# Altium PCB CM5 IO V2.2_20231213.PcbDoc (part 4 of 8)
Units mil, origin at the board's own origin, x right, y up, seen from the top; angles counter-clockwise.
Board outline 6299.61 x 3544.09 mil, 4 copper layers (Top, GND, Power, Bottom), stack 35.4 mil thick; 482 components, 404 nets, 1857 pads, 2731 vias.
Unrouted connection lines stored in the file: 1872.
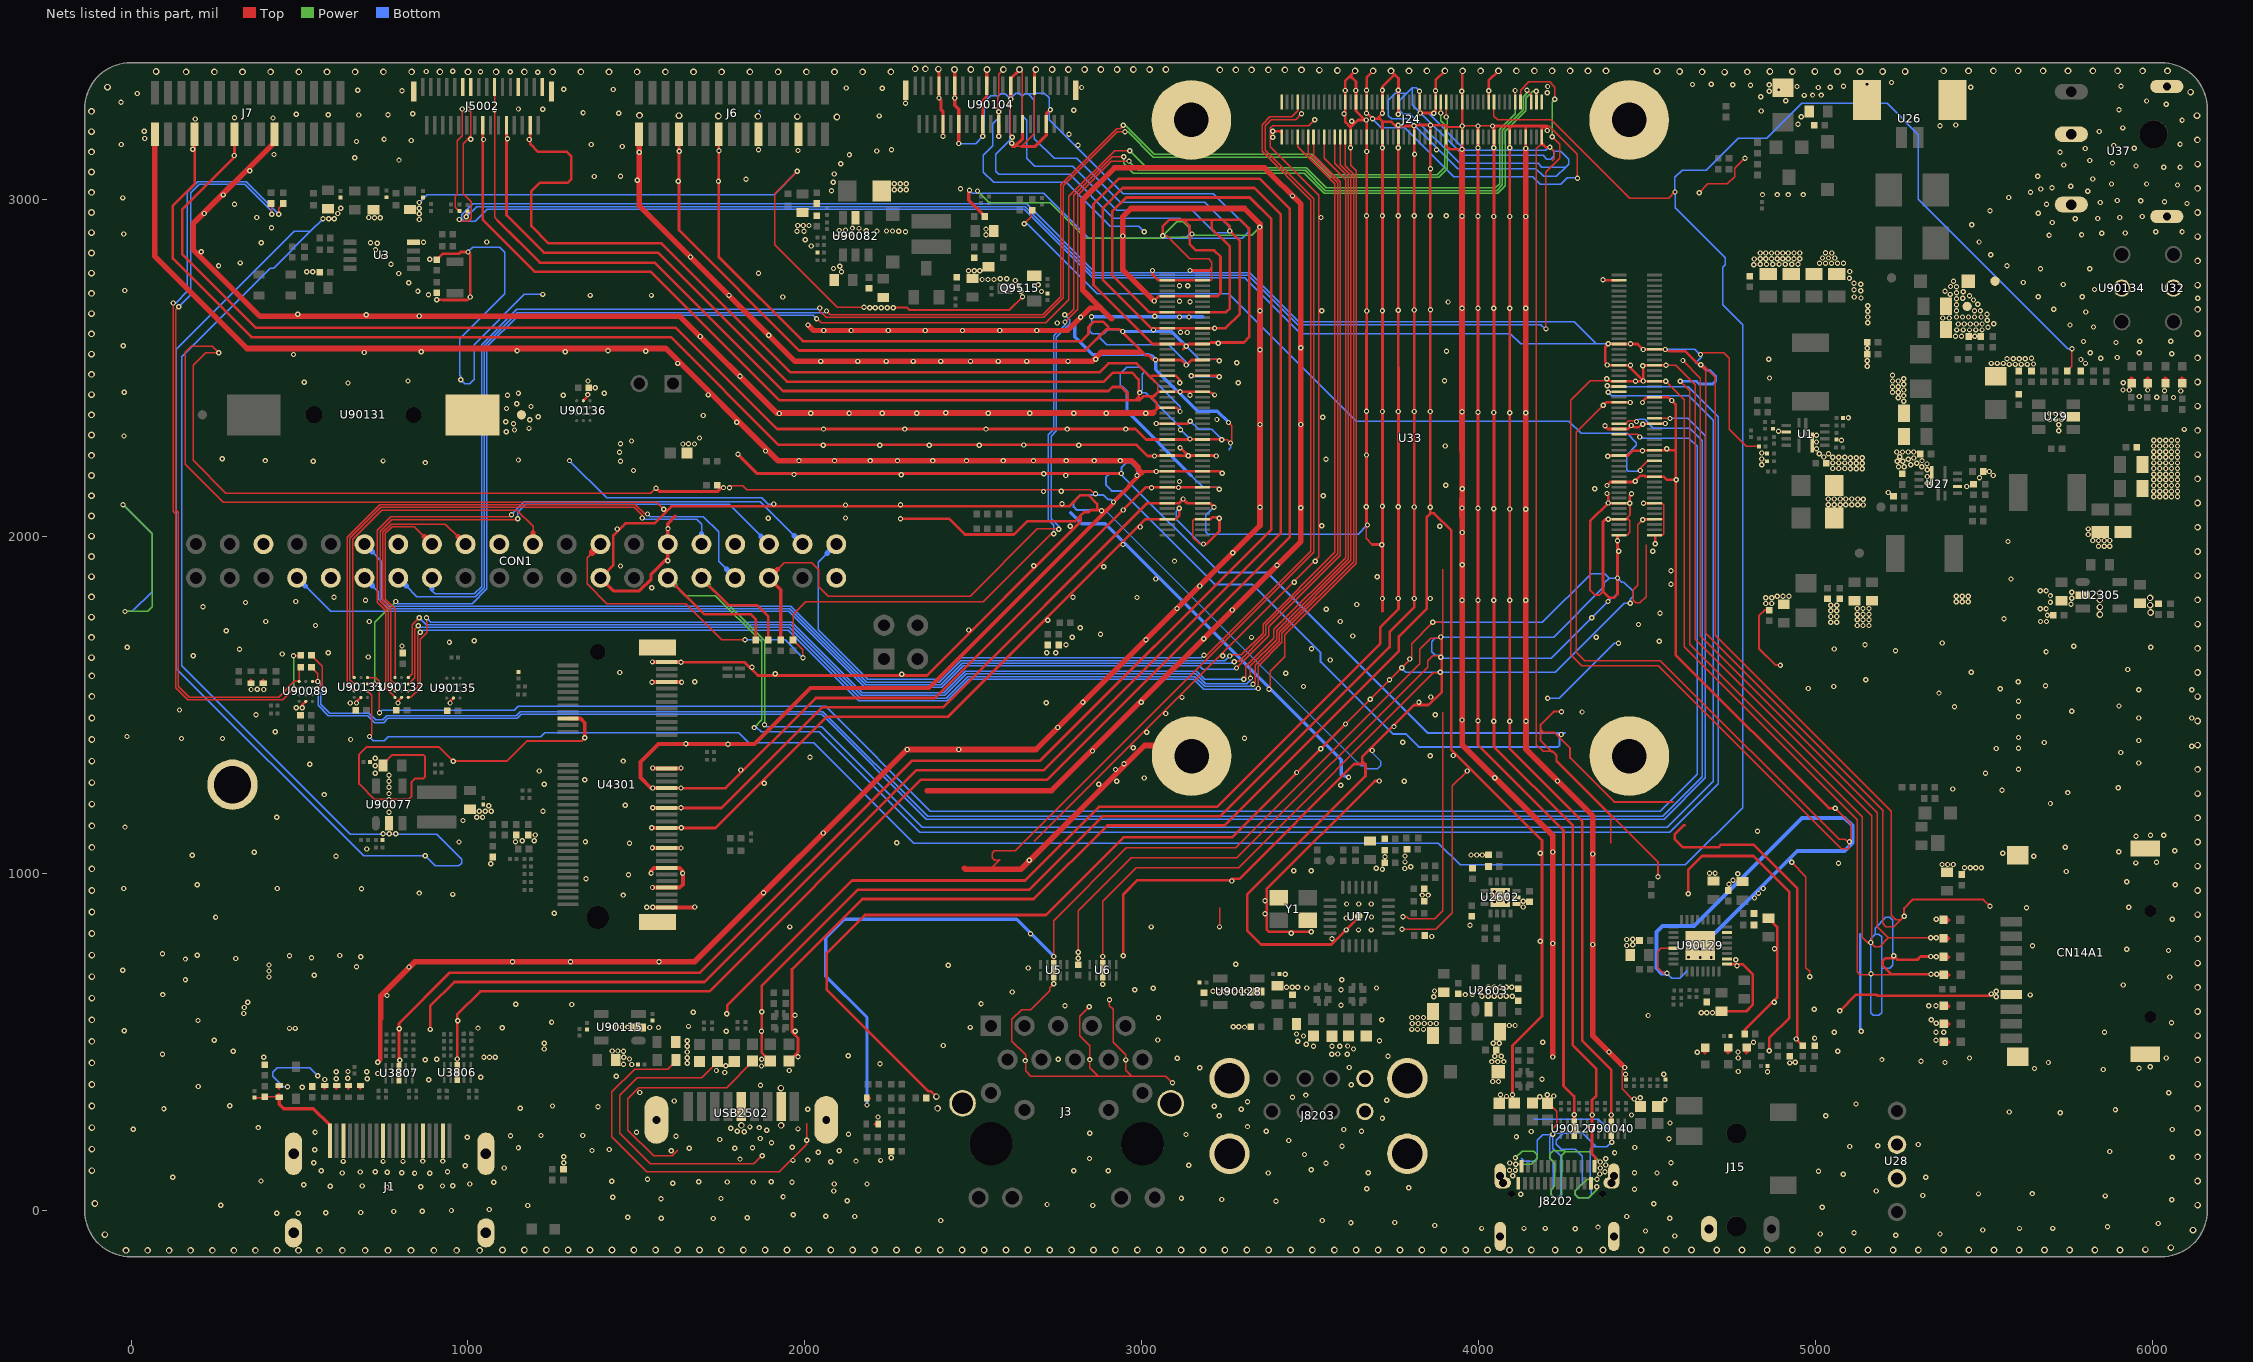
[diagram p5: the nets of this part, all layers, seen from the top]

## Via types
v1: diameter 15.75, hole 7.87, Top to Bottom, 2292 vias
v2: diameter 19.68, hole 11.81, Top to Bottom, 439 vias

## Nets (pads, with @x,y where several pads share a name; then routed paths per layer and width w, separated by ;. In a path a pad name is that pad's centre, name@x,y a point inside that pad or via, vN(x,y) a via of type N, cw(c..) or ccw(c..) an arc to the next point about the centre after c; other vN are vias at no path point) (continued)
GND: (continued)
  other v1: 4580.71,-76.77 5237.2,-74.8 5012.8,-70.87 5368.11,-70.87 5113.19,-66.93 4494.09,-62.01 5495.08,-59.06 4285.43,-55.12 4007.87,-54.13 4133.86,-54.13 4196.85,-54.13 5604.33,-54.13 5702.76,-54.13 4353.35,-50.2 5865.16,-49.21 3869.09,-45.28 6015.75,-39.37 3620.08,-37.4 3750,-36.42 2402.56,-30.51 3535.43,-30.51 1727.36,-24.61 1573.82,-23.62 4565.94,-23.62 1828.74,-22.64 1474.41,-20.67 2147.64,-18.7 4438.98,-18.7 2062.01,-17.72 1965.55,-13.78 432.09,-8.86 496.06,-8.86 577.76,-7.87 682.09,-6.89 779.53,-3.94 864.17,-2.95 950.79,-0.98 1062.99,1.97 5018.7,8.86 1177.17,13.78 2854.33,13.78 266.73,14.76 2718.5,16.73 4518.7,18.7 3397.64,26.57 2125,27.56 6056.1,30.51 3237.2,31.5 1572.83,33.46 1750.98,34.45 3117.13,35.43 1429.13,38.39 1935.04,39.37 5858.27,42.32 5316.93,43.31 4124.02,47.24 5482.28,48.23 5641.73,49.21 2085.63,57.09 5179.13,57.09 4461.61,62.01 3667.32,63.98 3791.34,66.93 759.84,68.9 860.24,69.88 591.54,70.87 686.02,71.85 924.21,71.85 954.72,72.83 512.8,75.79 1004.92,77.76 2086.61,77.76 2184.06,77.76 1607.28,79.72 4582.68,79.72 1076.77,82.68 1961.61,82.68 1769.69,83.66 1846.46,83.66 1685.04,84.65 1899.61,84.65 1426.18,85.63 385.83,86.61 1532.48,91.54 124.02,97.44 5325.79,97.44 4100.39,102.36 5080.71,106.3 4358.27,107.28 841.54,109.25 886.81,109.25 626.97,110.24 3375,110.24 4528.54,110.24 803.15,111.22 3671.26,111.22 4461.61,111.22 760.83,112.2 680.12,113.19 724.41,114.17 938.98,114.17 4374.02,114.17 5007.87,115.16 564.96,117.13 2797.24,117.13 2899.61,117.13 4090.55,118.11 4108.27,118.11 3501.97,120.08 1107.28,125 4360.24,125 992.13,131.89 3138.78,132.87 4375.98,133.86 3546.26,138.78 4091.54,139.76 542.32,140.75 1284.45,140.75 4569.88,140.75 2076.77,143.7 629.92,144.68 748.03,144.68 807.09,144.68 866.14,145.67 925.2,145.67 2151.57,145.67 1964.57,147.64 2224.41,147.64 2007.87,148.62 1807.09,151.57 4375.98,152.56 2844.49,153.54 2255.91,155.51 6057.09,157.48 1284.45,158.46 1873.03,161.42 3482.28,165.35 4402.56,170.28 2039.37,172.24 5872.05,174.21 1603.35,176.18 2101.38,176.18 1368.11,177.17 545.28,179.13 1419.29,180.12 1656.5,184.06 1791.34,184.06 1149.61,185.04 1844.49,185.04 4462.6,186.02 1962.6,187.01 5100.39,188.98 3593.5,189.96 5183.07,190.94 5304.13,194.88 1900.59,199.8 3436.02,206.69 2004.92,207.68 1747.05,209.65 4563.98,211.61 1867.13,212.6 998.03,216.54 4111.22,217.52 1617.13,219.49 1125.98,220.47 1216.54,221.46 1340.55,221.46 3130.91,224.41 2128.94,225.39 2845.47,228.35 546.26,231.3 1500,231.3 1819.88,232.28 4155.51,233.27 1799.21,234.25 3369.09,234.25 3651.57,234.25 1886.81,237.2 3598.43,239.17 6057.09,239.17 6.89,240.16 1979.33,241.14 1779.53,243.11 377.95,245.08 1864.17,245.08 1836.61,247.05 3312.99,248.03 4566.93,258.86 3713.58,272.64 2216.54,276.57 3229.33,280.51 5029.53,280.51 4336.61,282.48 4392.72,282.48 4452.76,282.48 4282.48,283.46 5725.39,289.37 5573.82,291.34 5888.78,298.23 2007.87,299.21 3294.29,299.21 97.64,301.18 1155.51,302.17 1385.83,307.09 3214.57,308.07 1250.98,309.06 293.31,310.04 5119.09,314.96 3312.99,321.85 1612.2,323.82 3726.38,325.79 4551.18,327.76 4478.35,333.66 3446.85,334.65 4180.12,336.61 4081.69,337.6 4222.44,338.58 3486.22,341.54 4063.98,342.52 4099.41,342.52 4202.76,342.52 6047.24,348.43 1509.84,349.41 507.87,365.16 199.8,367.13 1868.11,371.06 3621.06,372.05 4041.34,381.89 4058.07,381.89 883.86,386.61 574.8,387.8 4187.01,388.78 609.25,389.76 700.79,389.76 642.72,391.73 1037.4,394.09 1439.96,397.64 4435.04,403.54 4548.23,403.54 732.28,405.51 1761.81,408.46 609.25,410.43 699.8,410.43 4856.3,410.43 643.7,411.42 4769.69,411.42 1737.2,414.37 1953.74,414.37 5852.36,417.32 5648.62,420.28 5958.66,421.26 3171.26,422.24 3615.16,423.23 5992.13,425.2 1764.76,428.15 1870.87,427.95 1486.22,432.09 1461.61,433.07 2222.83,434.65 1650.59,436.02 4922.24,437.01 5382.87,437.99 5689.96,437.99 4938.98,438.98 4038.39,440.94 4056.1,440.94 4073.82,440.94 5312.01,441.93 2653.54,443.9 797.24,444.88 873.23,446.06 2951.77,445.87 2845.47,446.85 5195.87,446.85 907.48,447.83 1871.26,448.03 2751.97,447.83 968.5,448.82 1479.33,448.82 3104.33,450.79 4769.69,451.77 5455.71,451.77 6039.37,451.77 1650.59,452.76 393.7,453.74 1047.24,453.74 1063.98,453.74 1080.71,453.74 1462.6,453.74 4219.49,454.72 1979.33,455.71 3730.31,456.69 4047.24,456.69 4065.94,456.69 2128.74,457.87 93.5,462.6 3562.99,462.6 3609.25,462.6 3580.71,463.58 4647.64,468.5 1650.59,469.49 4385.83,469.49 4768.7,469.49 303.15,471.46 1461.61,471.46 5064.96,471.46 1428.15,472.44 1444.88,472.44 1226.38,478.35 3627.95,478.35 1650.59,486.22 3508.86,486.22 3563.98,486.22 3586.61,486.22 3610.24,487.2 2410.24,488.58 3487.2,492.13 1226.38,495.08 4042.32,495.08 4060.04,495.08 4188.98,498.03 4814.96,498.03 3462.6,500.98 1650.59,502.95 3704.72,502.95 247.05,503.94 5356.3,503.94 3047.24,504.92 4941.93,507.87 4996.06,509.84 3479.33,516.73 3458.66,522.64 5054.13,527.56 5356.3,527.56 5378.94,527.56 5856.3,527.56 1766.73,530.51 1871.06,530.51 1971.46,530.51 -19.69,532.48 3800.2,536.42 3817.91,536.42 3835.63,536.42 796.26,538.39 470.47,539.37 487.2,539.37 1029.53,540.35 1101.38,541.34 1539.76,542.13 1565.35,542.13 2490.16,542.32 1424.21,543.31 1440.94,543.31 1457.68,543.31 1474.41,543.31 3304.13,543.31 3270.67,544.29 3287.4,544.29 1654.53,545.28 4089.57,548.23 4107.28,548.23 3802.17,554.13 3819.88,554.13 3837.6,554.13 3855.31,554.13 3873.03,554.13 5357.28,555.12 6055.12,556.1 1248.03,558.07 969.49,562.01 198.82,562.99 3711.61,564.96 5342.52,564.96 3049.21,570.87 3800.2,571.85 3817.91,571.85 3835.63,571.85 4501.97,577.76 1970.47,578.74 1767.72,582.68 334.65,583.66 4659.45,585.63 4676.18,585.63 4692.91,585.63 1668.31,587.6 1872.05,588.58 4995.08,596.46 335.63,601.38 2771.65,606.3 5334.65,606.3 5356.3,606.3 3590.55,608.27 1308.07,610.24 1141.73,611.22 2522.64,612.2 346.46,617.13 4875.98,617.13 3866.14,632.87 5535.43,632.87 4008.86,634.84 4027.56,634.84 4045.28,634.84 4062.99,634.84 4080.71,634.84 4098.43,634.84 759.84,636.81 5635.83,638.78 94.49,639.76 3959.65,639.76 3980.31,639.76 2615.16,647.64 3210.63,649.61 3227.36,649.61 3244.09,649.61 3260.83,649.61 3277.56,649.61 3294.29,649.61 3311.02,649.61 5535.43,649.61 3868.11,650.59 4003.94,652.56 2978.35,654.53 3590.55,654.53 3033.07,658.27 3489.17,659.45 3695.87,659.45 3429.13,661.42 3445.87,661.42 3462.6,661.42 4027.56,661.42 4045.28,661.42 4062.99,661.42 4080.71,661.42 4097.44,661.42 5912.4,668.31 2883.86,670.47 161.42,684.06 3592.52,684.06 409.45,691.93 6050.2,691.93 543.31,696.85 3425.2,699.8 5358.27,699.8 5163.39,701.77 409.45,709.65 -24.61,711.61 2662.4,718.5 824.8,721.46 669.29,722.44 4765.75,725.39 409.45,727.36 2425.59,726.77 3278.54,729.33 1131.89,737.2 1304.13,737.2 1566.93,737.2 4761.81,743.11 161.42,745.08 311.02,747.05 2811.02,748.03 535.43,749.02 4656.5,750 4688.98,750 682.09,751.97 5357.28,751.97 2883.86,752.95 470.47,754.92 5231.3,754.92 619.09,755.91 196.85,756.89 93.5,760.83 2811.02,765.75 6046.26,770.67 4656.5,774.61 4687.99,774.61 5922.24,774.61 4622.05,775.59 4876.97,775.59 5642.72,784.45 4438.98,785.43 4456.69,787.4 4337.6,788.39 4219.49,791.34 4182.09,798.23 4438.98,803.15 4456.69,804.13 3563.98,805.12 5357.28,808.07 3860.24,812.01 2669.29,819.88 3442.91,821.85 3606.3,831.69 3642.72,831.69 3680.12,831.69 1954.72,840.55 3027.56,840.55 3973.43,845.47 5357.28,863.19 6057.09,863.19 3606.3,867.13 250.98,869.09 3681.1,870.08 3365.16,879.92 1255.91,880.91 5625,897.64 1530.51,898.62 5928.15,898.62 4131.89,899.61 3607.28,908.46 3643.7,908.46 3680.12,908.46 4080.71,914.37 4046.26,915.35 4131.89,916.34 3365.16,918.31 4817.91,926.18 1460.63,935.04 3831.69,935.04 3849.41,935.04 954.72,937.01 4829.72,939.96 855.31,940.94 1876.97,941.93 4046.26,945.87 4080.71,945.87 684.06,953.74 -21.65,954.72 434.06,954.72 4843.5,954.72 196.85,965.55 6065.94,965.55 4742.13,967.52 5922.24,974.41 4753.94,979.33 1350.39,983.27 1476.38,995.08 4767.72,998.03 4684.06,1000 4700.79,1000 5743.11,1004.92 3450.79,1006.89 3501.97,1006.89 3713.58,1011.81 3779.53,1013.78 3694.88,1014.76 5440.94,1015.75 5457.68,1015.75 5474.41,1015.75 5491.14,1015.75 3797.24,1018.7 5374.02,1025.59 5390.75,1025.59 5407.48,1025.59 1067.91,1027.56 5066.93,1029.53 5948.82,1030.51 6010.83,1032.48 3780.51,1033.46 2665.35,1038.39 3721.46,1049.21 608.27,1050.2 5646.65,1050.2 3780.51,1051.18 182.09,1053.15 3976.38,1054.13 3993.11,1054.13 4009.84,1054.13 4337.6,1057.09 4182.09,1059.06 5554.13,1059.06 366.14,1062.01 4219.49,1062.99 5898.62,1063.98 6064.96,1066.93 699.8,1071.85 5740.16,1076.77 1479.33,1088.58 2272.64,1090.55 973.43,1092.52 1140.75,1093.5 1348.43,1093.5 5099.41,1093.5 1161.42,1096.46 1196.85,1096.46 5949.8,1109.25 5993.11,1112.2 6032.48,1112.2 1199.8,1113.19 748.03,1117.13 766.73,1117.13 785.43,1117.13 2054.13,1119.09 4826.77,1124.02 1632.87,1134.84 -17.72,1136.81 985.24,1156.5 432.09,1166.34 1025.59,1166.34 1043.31,1166.34 765.75,1181.1 1033.46,1184.06 1051.18,1184.06 1068.9,1184.06 1222.44,1184.06 1631.89,1193.9 1062.01,1199.8 765.75,1200.79 1466.54,1201.77 5695.87,1206.69 573.82,1233.27 765.75,1236.22 5747.05,1239.17 5552.17,1246.06 5406.5,1250 1631.89,1252.95 5897.64,1253.94 765.75,1254.92 3589.57,1260.83 2871.54,1263.53 1226.38,1263.78 1878.94,1266.73 765.75,1272.64 2925.2,1272.64 3778.54,1272.64 4233.27,1273.62 1346.46,1277.56 3006.89,1282.48 4047.24,1283.46 765.75,1290.35 724.41,1296.26 5503.15,1296.46 3458.87,1298.99 1211.61,1303.15 1809.06,1306.1 2921.53,1307.83 5601.38,1308.07 724.41,1318.9 530.51,1322.83 2946.85,1324.8 5957.68,1326.77 1460.63,1332.68 724.41,1341.54 2014.76,1344.49 3855.31,1348.43 3924.21,1349.41 5904.53,1358.27 2853.13,1362.48 2303.15,1367.13 2456.69,1367.13 3530.7,1369.52 5535.43,1370.08 5601.38,1371.06 2974.13,1371.95 6115.16,1376.97 1771.65,1382.87 1646.65,1383.86 5677.17,1387.8 3773.62,1388.78 5957.68,1393.7 651.57,1396.65 149.61,1399.61 271.65,1399.61 3304.13,1400.59 5601.38,1402.56 -11.81,1405.51 4244.09,1411.42 3014.64,1418.58 428.15,1419.29 2750.04,1432.18 3748.03,1435.04 4044.29,1450.79 4091.54,1450.79 3997.05,1452.76 3949.8,1454.72 5957.68,1460.63 6115.16,1460.63 5601.38,1464.57 371.06,1470.47 3870.08,1470.47 3070.75,1473.81 4306.1,1478.35 5758.86,1480.31 143.7,1484.25 490.16,1491.14 5411.42,1494.09 5899.61,1496.06 650.59,1504.92 2715.55,1505.91 2824.8,1506.89 2998.18,1507.53 3821.91,1507.23 5601.38,1509.84 3677.41,1516.57 3118.84,1521.61 3857.28,1522.64 5365.16,1534.45 5957.68,1544.29 6115.16,1544.29 356.3,1545.28 393.7,1545.28 375,1546.26 3376.97,1546.26 5547.24,1547.24 4977.36,1548.23 3479.33,1554.13 5053.15,1554.13 5681.1,1556.1 1673.23,1568.11 5600.39,1567.91 3734.61,1574.03 5147.64,1573.82 2287.4,1590.55 1912.2,1592.13 3427.17,1593.5 1450,1595.67 5460.63,1596.46 5925.2,1604.33 1842.91,1611.42 3559.06,1632.87 3794.31,1635.56 703.74,1641.73 185.04,1645.67 3239.75,1645.45 448.82,1650.59 585.63,1654.53 2717.52,1654.53 2744.09,1654.53 5683.07,1657.48 5236.22,1660.43 321.85,1664.37 5054.13,1665.35 3502.95,1666.34 -10.83,1670.28 5994.09,1670.28 5764.76,1673.23 804.13,1674.21 2774.61,1678.15 5145.67,1678.15 5375,1683.07 944.88,1685.04 4535.43,1687.99 1018.7,1689.96 3011.97,1692.87 3183.14,1695.59 2793.31,1699.8 3325.05,1699.7 4348.43,1699.8 3625.98,1703.74 2876.97,1708.66 282.48,1719.49 2486.22,1721.46 2816.93,1728.35 547.24,1735.24 5123.03,1735.24 5139.76,1735.24 5157.48,1735.24 4473.43,1738.19 5044.29,1745.08 5062.01,1745.08 399.61,1747.05 706.69,1747.05 3588.58,1747.05 5666.34,1747.05 5684.06,1747.05 2720.47,1750.98 5123.03,1751.97 5139.76,1751.97 5157.48,1751.97 5558.07,1754.92 4334.65,1757.87 5044.29,1761.81 5062.01,1761.81 5687.01,1765.75 5123.03,1768.7 5139.76,1768.7 5157.48,1768.7 4537.4,1771.65 5044.29,1778.54 5062.01,1778.54 3268.12,1780.89 3547.24,1783.46 5665.35,1784.45 5683.07,1784.45 3104.13,1785.67 5123.03,1785.43 5139.76,1785.43 5157.48,1785.43 213.58,1790.35 5044.29,1795.28 5062.01,1795.28 3637.8,1797.24 5756.89,1798.23 4851.38,1800.2 4869.09,1800.2 339.57,1803.15 5695.87,1804.13 5416.34,1805.12 5434.06,1805.12 5451.77,1805.12 489.17,1806.1 695.87,1810.04 3949.8,1810.04 3997.05,1810.04 4044.29,1810.04 4091.54,1810.04 3713.58,1814.96 3760.83,1814.96 3808.07,1814.96 3855.31,1814.96 5758.86,1815.94 4851.38,1816.93 4869.09,1816.93 2985.24,1817.91 602.36,1818.9 2795.28,1818.9 4884.84,1821.85 4902.56,1821.85 4920.28,1821.85 5416.34,1821.85 5434.06,1821.85 5451.77,1821.85 5695.87,1823.82 5758.86,1833.66 5665.35,1838.58 5683.07,1838.58 1545.28,1847.44 3171.26,1852.36 4569.88,1857.28 3451.6,1863.58 3041.34,1873.03 5578.74,1873.03 3697.83,1879.92 4569.88,1897.64 2886.81,1909.45 1452.76,1911.42 2679.13,1912.4 3400.61,1913.79 3514.56,1925.37 3096.46,1926.18 1592.52,1927.17 3269.79,1950.83 4415.35,1955.71 4515.75,1955.71 5838.58,1970.47 5855.31,1970.47 5872.05,1970.47 2943.9,1975.39 5569.88,1984.25 5821.85,1987.2 5838.58,1987.2 5855.31,1987.2 5872.05,1987.2 5808.07,2004.92 1442.91,2021.26 5808.07,2021.65 1593.5,2022.64 2995.08,2027.56 2787.4,2029.53 3883.86,2029.53 3533.46,2031.5 1890.75,2053.15 2120.08,2054.13 2879.92,2075.79 2944.88,2077.76 4044.29,2081.69 4091.54,2080.71 3997.05,2082.68 3471.46,2084.65 3350.39,2085.63 3855.31,2085.63 3808.07,2086.61 3665.35,2087.6 3760.83,2087.6 3713.58,2088.58 2120.08,2092.52 5140.75,2092.52 2283.46,2093.5 5036.42,2093.5 5054.13,2093.5 5071.85,2093.5 5088.58,2093.5 5106.3,2093.5 5124.02,2093.5 2762.8,2096.46 5140.75,2109.25 5036.42,2110.24 5054.13,2110.24 5071.85,2110.24 5088.58,2110.24 5106.3,2110.24 5124.02,2110.24 6002.95,2117.13 6020.67,2117.13 6038.39,2117.13 6055.12,2117.13 6072.83,2117.13 3538.39,2120.08 4379.92,2126.97 5214.57,2129.92 2707.68,2132.87 2760.24,2133.86 6002.95,2133.86 6020.67,2133.86 6038.39,2133.86 6055.12,2133.86 6072.83,2133.86 4343.5,2140.75 3028.54,2143.7 5447.83,2147.64 6002.95,2150.59 6020.67,2150.59 6038.39,2150.59 6055.12,2150.59 6072.83,2150.59 3901.57,2151.57 5330.71,2157.48 3111.22,2162.4 6002.95,2167.32 6020.67,2167.32 6038.39,2167.32 6055.12,2167.32 6072.83,2167.32 5485.24,2173.23 5330.71,2177.17 2773.62,2180.12 5526.57,2180.12 2285.43,2182.09 1967.52,2183.07 6002.95,2184.06 6020.67,2184.06 6038.39,2184.06 6055.12,2184.06 6072.83,2184.06 2708.66,2185.04 5514.76,2191.93 1491.14,2194.88 5330.71,2196.85 5102.36,2199.8 5120.08,2199.8 5137.8,2199.8 5050.2,2200.79 5067.91,2200.79 5085.63,2200.79 6002.95,2200.79 6020.67,2200.79 6038.39,2200.79 6055.12,2200.79 6072.83,2200.79 5245.08,2205.71 5261.81,2205.71 5313.98,2205.71 4839.57,2211.61 5281.5,2211.61 5329.72,2214.57 5102.36,2216.54 5120.08,2216.54 5137.8,2216.54 5299.21,2216.54 5050.2,2217.52 5067.91,2217.52 5085.63,2217.52 6002.95,2217.52 6020.67,2217.52 6038.39,2217.52 6055.12,2217.52 6072.83,2217.52 873.03,2218.5 540.35,2222.44 1452.76,2222.44 5241.14,2222.44 5257.87,2222.44 748.03,2223.43 398.62,2224.41 1982.28,2224.41 2087.6,2224.41 2193.9,2224.41 2274.61,2224.41 2378.94,2224.41 2479.33,2224.41 2588.58,2224.41 2678.15,2224.41 2775.59,2224.41 2858.27,2224.41 2936.02,2224.41 5314.96,2224.41 1149.61,2226.38 3546.26,2228.35 5273.62,2228.35 4839.57,2229.33 270.67,2230.31 5290.35,2232.28 5102.36,2233.27 5120.08,2233.27 5137.8,2233.27 5050.2,2234.25 5067.91,2234.25 5085.63,2234.25 6002.95,2234.25 6020.67,2234.25 6038.39,2234.25 6055.12,2234.25 6072.83,2234.25 5023.62,2235.24 5249.02,2236.22 3666.34,2241.14 5009.84,2245.08 5037.4,2245.08 4839.57,2247.05 1449.8,2249.02 5240.16,2250 5256.89,2250 5273.62,2250 5290.35,2250 6002.95,2250.98 6020.67,2250.98 6038.39,2250.98 6055.12,2250.98 6072.83,2250.98 1882.87,2252.95 4557.09,2259.84 5001.97,2259.84 3899.61,2267.72 6002.95,2267.72 6020.67,2267.72 6038.39,2267.72 6055.12,2267.72 6072.83,2267.72 2054.13,2269.68 2221.46,2269.68 2369.09,2269.68 2516.73,2269.68 2812.01,2269.68 2649.61,2270.87 1637.8,2273.62 1672.24,2273.62 1452.76,2274.61 1654.53,2274.61 5001.97,2279.53 1485.24,2282.48 5075.79,2284.45 6002.95,2284.45 6020.67,2284.45 6038.39,2284.45 6055.12,2284.45 6072.83,2284.45 1687.01,2291.34 -20.67,2297.24 5001.97,2299.21 1113.19,2310.04 4888.78,2311.02 5720.47,2312.99 1137.8,2314.96 6093.5,2316.93 2055.12,2317.91 2296.26,2317.91 2537.4,2317.91 2778.54,2317.91 2951.77,2317.91 1181.1,2319.88 3350.39,2331.69 3471.46,2331.69 5720.47,2330.71 1134.84,2333.66 1797.24,2338.58 1112.2,2339.57 1183.07,2345.47 3222.44,2346.46 5693.9,2346.46 5711.61,2346.46 5729.33,2346.46 5096.46,2351.38 3536.42,2353.35 1208.66,2354.33 1697.83,2358.27 1923.23,2364.17 5693.9,2364.17 5711.61,2364.17 5729.33,2364.17 2016.73,2365.16 2130.91,2365.16 2229.33,2365.16 2331.69,2365.16 2544.29,2365.16 2667.32,2365.16 2797.24,2365.16 3010.83,2365.16 2417.32,2366.14 4091.54,2366.14 4044.29,2367.13 3997.05,2368.11 3713.58,2370.08 3760.83,2370.08 3808.07,2370.08 3855.31,2370.08 3666.34,2371.06 1114.17,2378.94 1187.01,2384.84 1144.69,2392.72 5260.83,2400.59 5244.09,2410.43 6061.02,2411.42 6011.81,2412.4 5959.65,2414.37 5260.83,2417.32 1117.13,2418.31 1282.48,2418.31 3142.72,2418.31 1712.6,2419.29 1149.61,2424.21 1404.53,2424.21 -19.69,2427.17 5227.36,2427.17 5244.09,2427.17 6082.68,2431.1 6034.45,2432.09 5260.83,2434.06 5911.42,2434.06 5930.12,2434.06 5984.25,2434.06 1377.95,2440.94 5227.36,2443.9 5244.09,2443.9 5260.83,2450.79 643.7,2454.72 513.78,2456.69 3285.43,2455.71 5912.4,2455.71 4464.57,2459.65 821.85,2460.63 1356.3,2460.63 5227.36,2460.63 5244.09,2460.63 3897.64,2461.61 5260.83,2467.52 4862.2,2469.49 1807.09,2474.41 5227.36,2477.36 5152.56,2503.94 4486.22,2505.91 4449.8,2506.89 4380.91,2507.87 5573.82,2509.84 5591.54,2509.84 5609.25,2509.84 5626.97,2509.84 5645.67,2510.83 1622.05,2512.8 5520.67,2512.8 5538.39,2512.8 5556.1,2512.8 5800.2,2512.8 3281.5,2514.76 2047.24,2518.7 2156.5,2518.7 2241.14,2518.7 2320.87,2518.7 2402.56,2518.7 2491.14,2518.7 2573.82,2518.7 2658.46,2518.7 2780.51,2518.7 5152.56,2520.67 5786.42,2524.61 2863.19,2525.59 4860.24,2525.59 5566.93,2526.57 5585.63,2526.57 5603.35,2526.57 5621.06,2526.57 5639.76,2528.54 5845.47,2528.54 5894.69,2530.51 482.28,2539.37 6056.1,2541.34 5813.98,2544.29 5959.65,2544.29 691.93,2545.28 861.22,2547.24 1288.39,2547.24 1527.56,2549.21 3903.54,2549.21 1145.67,2550.2 1415.35,2550.2 3350.39,2553.15 5152.56,2558.07 3471.46,2559.06 -22.64,2564.96 4449.8,2570.87 3226.38,2572.83 5890.75,2574.8 5794.29,2577.76 5960.63,2578.74 6053.15,2578.74 1688.98,2592.52 5414.37,2593.5 5432.09,2593.5 5471.46,2593.5 1892.72,2596.46 3134.84,2604.33 3114.17,2605.31 2056.1,2610.24 2136.81,2610.24 2247.05,2610.24 2357.28,2610.24 2467.52,2610.24 2577.76,2610.24 2687.99,2610.24 5418.31,2612.2 5437.01,2612.2 5455.71,2612.2 5474.41,2612.2 5493.11,2612.2 3215.55,2617.13 5510.83,2620.08 5823.82,2621.06 5753.94,2626.97 5422.24,2629.92 5439.96,2629.92 5457.68,2629.92 5475.39,2629.92 5493.11,2629.92 5527.56,2630.91 2749.02,2632.87 5153.54,2633.86 5508.86,2640.75 5375.98,2647.64 5395.67,2647.64 3111.22,2650.59 3139.76,2650.59 5153.54,2650.59 5417.32,2650.59 5435.04,2650.59 5452.76,2650.59 5470.47,2650.59 5490.16,2650.59 3038.39,2652.56 855.31,2653.54 697.83,2657.48 495.08,2658.46 5507.87,2658.46 5801.18,2665.35 5153.54,2667.32 3667.32,2668.31 3350.39,2669.29 3533.46,2669.29 3713.58,2669.29 5417.32,2669.29 5470.47,2669.29 5488.19,2669.29 3760.83,2670.28 3808.07,2671.26 3856.3,2672.24 5705.71,2673.23 3997.05,2676.18 4044.29,2676.18 4091.54,2676.18 2191.93,2678.15 2208.66,2678.15 2226.38,2678.15 2244.09,2678.15 5153.54,2684.06 5417.32,2687.01 5480.31,2687.99 3908.46,2694.88 3142.72,2695.87 3111.22,2696.85 5467.52,2700.79 5417.32,2704.72 5133.86,2706.69 5436.02,2705.71 6132.87,2705.71 1934.06,2709.65 5114.17,2709.65 5659.45,2710.63 5790.35,2710.63 5455.71,2713.58 1363.19,2714.57 1544.29,2714.57 1774.61,2714.57 882.87,2716.54 5398.62,2717.52 5417.32,2722.44 5437.01,2725.39 2701.77,2726.38 851.38,2727.36 2640.75,2727.36 5382.87,2727.36 5132.87,2728.35 -18.7,2729.33 5113.19,2731.3 5826.77,2732.28 5417.32,2740.16 5399.61,2741.14 2631.89,2743.11 3111.22,2743.11 3135.83,2743.11 2691.93,2746.06 5734.25,2747.05 5132.87,2748.03 5113.19,2750.98 823.82,2751.97 5615.16,2752.95 5408.46,2756.89 2624.02,2758.86 2525.59,2761.81 2543.31,2761.81 2561.02,2761.81 2579.72,2763.78 2598.43,2763.78 5099.41,2765.75 794.29,2779.53 1862.2,2780.51 521.65,2784.45 539.37,2784.45 2108.27,2784.45 5100.39,2785.43 2485.24,2787.4 2501.97,2787.4 2518.7,2787.4 5666.34,2793.31 5812.99,2793.31 2084.65,2794.29 2103.35,2801.18 259.84,2802.17 5566.93,2802.17 4815.94,2805.12 771.65,2807.09 4834.65,2807.09 4853.35,2807.09 4872.05,2807.09 4890.75,2807.09 4909.45,2807.09 4928.15,2807.09 4946.85,2807.09 5010.83,2810.04 5028.54,2810.04 5046.26,2810.04 5063.98,2810.04 5081.69,2810.04 323.82,2811.02 886.81,2821.85 4816.93,2822.83 4834.65,2823.82 4851.38,2823.82 4868.11,2823.82 4884.84,2823.82 4901.57,2823.82 4918.31,2823.82 4935.04,2823.82 4951.77,2823.82 5019.69,2825.79 5037.4,2825.79 5056.1,2825.79 1660.43,2828.74 748.03,2829.72 5518.7,2835.63 4834.65,2840.55 4851.38,2840.55 4868.11,2840.55 4884.84,2840.55 4901.57,2840.55 4918.31,2840.55 4935.04,2840.55 4951.77,2840.55 5047.24,2840.55 5028.54,2841.54 208.66,2844.49 725.39,2850.39 2018.7,2861.22 730.31,2869.09 386.81,2871.06 710.63,2871.06 868.11,2872.05 1056.1,2873.03 5484.25,2873.03 2000.98,2879.92 2092.52,2886.81 2114.17,2887.8 2942.91,2890.75 5691.93,2892.72 2537.4,2894.68 5788.39,2894.68 -21.65,2896.65 2134.84,2897.64 5848.43,2898.62 5918.31,2899.61 2298.23,2903.54 6008.86,2903.54 6086.61,2903.54 1976.38,2904.53 1997.05,2904.53 2278.54,2904.53 2213.58,2905.51 2242.13,2905.51 2259.84,2905.51 2182.09,2906.5 2101.38,2907.48 2120.08,2908.46 2537.4,2911.42 2160.43,2913.39 2140.75,2914.37 416.93,2915.75 1978.35,2922.24 1995.08,2922.24 2011.81,2922.24 5462.6,2924.21 5701.77,2931.1 855.31,2939.96 586.61,2941.93 603.35,2941.93 5769.69,2941.93 5836.61,2942.91 722.44,2944.88 739.17,2944.88 373.03,2945.87 705.71,2945.87 3531.5,2945.87 5901.57,2945.87 4044.29,2948.82 4091.54,2948.82 5968.5,2948.82 3997.05,2949.8 3666.34,2950.79 3713.58,2950.79 3760.83,2950.79 3808.07,2950.79 3855.31,2950.79 3902.56,2950.79 855.31,2956.69 217.52,2957.68 613.19,2957.68 5659.45,2958.66 5516.73,2965.55 622.05,2973.43 855.31,2973.43 307.09,2985.24 5684.06,2985.24 6101.38,2987.2 5843.5,2990.16 6034.45,2992.13 5963.58,2995.08 5894.69,2996.06 -24.61,3003.94 5571.85,3004.92 3446.85,3009.84 273.62,3012.8 4841.54,3013.78 4884.84,3013.78 4918.31,3013.78 4962.6,3013.78 5636.81,3020.67 5807.09,3023.62 2078.74,3025.59 2264.76,3028.54 2282.48,3028.54 2300.2,3028.54 5667.32,3030.51 2461.61,3031.5 5700.79,3034.45 5755.91,3038.39 6072.83,3042.32 5876.97,3045.28 5981.3,3045.28 2264.76,3046.26 2282.48,3046.26 2300.2,3046.26 2083.66,3050.2 1624.02,3053.15 1743.11,3053.15 1501.97,3056.1 1824.8,3059.06 5821.85,3060.04 1374.8,3067.32 1452.36,3068.5 5658.46,3067.91 2086.61,3074.8 352.36,3084.65 3856.3,3090.55 6032.48,3094.49 6080.71,3094.49 5949.8,3098.43 5735.24,3101.38 2106.3,3105.31 5879.92,3107.28 5812.99,3115.16 795.28,3116.14 664.37,3123.03 306.1,3129.92 2131.89,3131.89 424.21,3132.87 3809.06,3133.86 1507.87,3139.76 5724.41,3139.76 3667.32,3141.73 1626.97,3142.72 1745.08,3143.7 2212.6,3143.31 1979.33,3144.68 1862.2,3146.65 2256.89,3146.65 3874.02,3146.65 183.07,3148.62 5799.21,3150.59 5944.88,3151.57 3713.58,3152.56 3760.83,3152.56 3997.05,3152.56 4044.29,3152.56 1457.87,3156.3 5883.86,3159.45 2810.04,3160.43 -28.54,3162.4 1365.35,3162.2 6080.71,3163.39 669.29,3171.26 831.69,3174.21 1046.26,3177.17 750.98,3178.15 1007.87,3178.15 1117.13,3179.13 40.35,3180.12 3387.8,3184.06 2783.46,3192.91 5840.55,3200.79 39.37,3201.77 5910.43,3211.61 5368.11,3218.5 5415.35,3220.47 4946.85,3222.44 3623.03,3231.3 6086.61,3234.25 190.94,3238.19 421.26,3241.14 307.09,3242.13 4956.69,3245.08 2220.08,3247.24 676.18,3250 585.63,3250.98 762.8,3250.98 490.16,3251.97 835.63,3253.94 3599.41,3253.94 1447.24,3254.72 3666.34,3254.92 3713.58,3254.92 3866.14,3254.92 1341.54,3256.89 4837.6,3261.81 2797.24,3263.78 1078.74,3265.75 5899.61,3265.75 1221.46,3266.73 1149.61,3267.72 6039.37,3281.5 2298.23,3284.45 -29.53,3287.4 5981.3,3291.34 4910.43,3292.32 4836.61,3304.13 4965.55,3308.07 4990.16,3309.06 5015.75,3309.06 18.7,3313.98 4202.76,3315.94 3948.82,3320.87 4861.22,3320.87 804.13,3321.85 3871.06,3321.85 4029.53,3321.85 3603.35,3322.83 3634.84,3322.83 673.23,3323.82 3666.34,3323.82 3713.58,3323.82 3760.83,3323.82 1431.1,3325.59 4889.76,3324.8 1283.86,3326.38 2229.53,3329.13 2122.83,3329.92 2820.87,3331.69 5006.89,3331.69 5042.32,3332.68 5459.65,3332.68 4203.74,3334.65 4943.9,3334.65 5081.69,3335.63 5905.51,3335.63 4806.1,3338.58 4752.95,3339.57 4861.22,3339.57 4633.86,3340.55 4688.98,3341.54 5151.57,3341.54 5224.41,3346.46 1207.09,3376.38 1037.01,3378.35 875.98,3379.13 1125.59,3378.74 954.33,3379.92
  other v2: -14.76,-119.09 49.21,-119.09 113.19,-119.09 177.17,-119.09 241.14,-119.09 305.12,-119.09 369.09,-119.09 433.07,-119.09 497.05,-119.09 559.06,-119.09 626.97,-119.09 694.88,-119.09 762.8,-119.09 830.71,-119.09 898.62,-119.09 966.54,-119.09 1034.45,-119.09 1102.36,-118.11 1167.32,-118.11 1232.28,-118.11 1297.24,-118.11 1362.2,-118.11 1427.17,-118.11 1492.13,-118.11 1557.09,-118.11 1622.05,-118.11 1687.01,-118.11 1751.97,-118.11 1816.93,-118.11 1881.89,-118.11 1946.85,-118.11 2011.81,-118.11 2076.77,-118.11 2141.73,-118.11 2206.69,-118.11 2271.65,-118.11 2336.61,-118.11 2401.57,-118.11 2466.54,-118.11 2531.5,-118.11 2596.46,-118.11 2661.42,-118.11 2726.38,-118.11 2791.34,-118.11 2856.3,-118.11 2921.26,-118.11 2986.22,-118.11 3051.18,-118.11 3116.14,-118.11 3181.1,-118.11 3246.06,-118.11 3311.02,-118.11 3375.98,-118.11 3440.94,-118.11 3505.91,-118.11 3570.87,-118.11 3635.83,-118.11 3700.79,-118.11 3765.75,-118.11 3830.71,-118.11 3895.67,-118.11 3960.63,-118.11 4025.59,-118.11 4090.55,-118.11 4155.51,-118.11 4226.38,-118.11 4297.24,-118.11 4368.11,-118.11 4481.3,-118.11 4556.1,-118.11 4630.91,-118.11 4705.71,-118.11 4780.51,-118.11 4855.31,-118.11 4930.12,-118.11 5004.92,-118.11 5079.72,-118.11 5154.53,-118.11 5229.33,-118.11 5304.13,-118.11 5378.94,-118.11 5453.74,-118.11 5528.54,-118.11 5603.35,-118.11 5678.15,-118.11 5752.95,-118.11 5827.76,-118.11 5902.56,-118.11 5977.36,-117.13 6053.15,-111.22 -77.76,-72.83 6119.09,-59.06 6132.87,14.76 -107.28,19.68 6132.87,86.61 -116.14,117.13 6132.87,158.46 -116.14,181.1 6132.87,230.31 -116.14,245.08 1811.02,251.97 1929.13,251.97 2393.7,302.17 6132.87,302.17 -116.14,309.06 1928.15,362.2 -116.14,373.03 6132.87,374.02 -116.14,437.01 6132.87,445.87 -116.14,500.98 6132.87,517.72 -116.14,564.96 6132.87,589.57 -116.14,628.94 6132.87,661.42 -116.14,692.91 6132.87,733.27 -116.14,756.89 6132.87,805.12 -116.14,820.87 6132.87,876.97 -116.14,884.84 -116.14,948.82 6132.87,948.82 -116.14,1012.8 6132.87,1020.67 -116.14,1076.77 6132.87,1092.52 -116.14,1140.75 6132.87,1164.37 -116.14,1204.72 6132.87,1236.22 -116.14,1268.7 6132.87,1308.07 -116.14,1332.68 6132.87,1379.92 -116.14,1396.65 6132.87,1451.77 -116.14,1460.63 6132.87,1523.62 -116.14,1524.61 -116.14,1585.63 6132.87,1595.47 -117.13,1639.76 6132.87,1667.32 -117.13,1699.8 6132.87,1739.17 -117.13,1759.84 5842.52,1767.72 5993.11,1773.62 5842.52,1789.37 5992.13,1795.28 5842.52,1811.02 6132.87,1811.02 5992.13,1816.93 -117.13,1819.88 5842.52,1832.68 -117.13,1879.92 6132.87,1882.87 -117.13,1939.96 6132.87,1954.72 -117.13,2000 6132.87,2026.57 -117.13,2060.04 6132.87,2098.43 -117.13,2120.08 6132.87,2170.28 -117.13,2180.12 -117.13,2240.16 6132.87,2242.13 -117.13,2300.2 6132.87,2313.98 -117.13,2360.24 6132.87,2385.83 -117.13,2420.28 6132.87,2457.68 -117.13,2480.31 6132.87,2529.53 -117.13,2540.35 -117.13,2600.39 6132.87,2601.38 -117.13,2660.43 6132.87,2673.23 -117.13,2720.47 6132.87,2745.08 -117.13,2780.51 6132.87,2816.93 -117.13,2840.55 6132.87,2888.78 -117.13,2900.59 -117.13,2960.63 6132.87,2960.63 -117.13,3020.67 6132.87,3032.48 -117.13,3080.71 6132.87,3104.33 -117.13,3140.75 6131.89,3176.18 -117.13,3200.79 2094.49,3244.09 1977.36,3245.08 1860.24,3246.06 1743.11,3247.05 1625.98,3248.03 6130.91,3248.03 1508.86,3249.02 -117.13,3260.83 6112.2,3317.91 -69.88,3332.68 4729.33,3376.97 163.39,3377.95 247.05,3377.95 330.71,3377.95 414.37,3377.95 498.03,3377.95 581.69,3377.95 665.35,3377.95 749.02,3377.95 832.68,3377.95 916.34,3377.95 1000,3377.95 1083.66,3377.95 1167.32,3377.95 1250.98,3377.95 1334.65,3377.95 1418.31,3377.95 1501.97,3377.95 1585.63,3377.95 1669.29,3377.95 1752.95,3377.95 1836.61,3377.95 1920.28,3377.95 2003.94,3377.95 2087.6,3377.95 2171.26,3377.95 2254.92,3377.95 4662.4,3377.95 4796.26,3377.95 74.8,3378.94 4595.47,3378.94 4863.19,3378.94 4930.12,3378.94 4997.05,3378.94 5063.98,3378.94 5130.91,3378.94 5197.83,3378.94 5264.76,3378.94 4528.54,3379.92 3792.32,3380.91 3845.47,3380.91 4004.92,3380.91 4111.22,3380.91 4164.37,3380.91 4217.52,3380.91 4270.67,3380.91 4323.82,3380.91 4376.97,3380.91 5378.94,3380.91 5452.76,3380.91 5526.57,3380.91 5600.39,3380.91 5674.21,3380.91 5748.03,3380.91 5821.85,3380.91 5895.67,3380.91 5969.49,3380.91 6043.31,3380.91 3579.72,3381.89 3526.57,3382.87 3231.3,3383.86 3278.54,3383.86 3325.79,3383.86 3375,3383.86 3424.21,3383.86 3473.43,3383.86 2492.13,3384.84 2733.27,3384.84 2781.5,3384.84 2829.72,3384.84 2877.95,3384.84 2926.18,3384.84 2974.41,3384.84 3022.64,3384.84 3070.87,3384.84 2326.77,3386.81 2357.28,3386.81
GPIO0_C2: CON1.12 J24.93 | length 4569.6
  Top w3.94: v1(3260.09,1644.63) 3260.09,1647.64 3295.28,1647.64 3360.24,1712.6 3360.24,1739.17 3572.83,1951.77 3572.83,3045.3 3462.01,3156.13 J24.93@3462.01,3184.65
  Bottom w3.94: 715.76,1953.54 743.31,1925.99 743.31,1815.75 766.73,1792.32 1958.35,1792.32 2183.75,1566.93 2398.93,1566.93 2462.91,1630.91 3246.36,1630.91 v1(3260.09,1644.63)
  Bottom w15.75: CON1.12@692.94,1976.36 715.76,1953.54
GPIO0_C7: CON1.31 R95590.2 U33.56 | length 5276.6
  Top w3.94: v1(4383.86,2427.17) 4383.86,2428.54 U33.56@4415.75,2428.54
  Top w7.87: CON1.31@1692.94,1876.36 1692.94,1874.97 1772.64,1795.28 1858.27,1795.28 1890.75,1762.8 R95590.2@1890.75,1691.93
  Power w3.94: 1712.61,1856.69 1879.92,1689.38 v1(1879.92,1440.94)
  Power w15.75: CON1.31@1692.94,1876.36 1712.61,1856.69
  Bottom w3.94: v1(1879.92,1440.94) 1885.83,1435.04 2050.2,1435.04 2348.43,1136.81 4559.42,1136.81 4694.88,1272.27 4694.88,2343.5 4622.05,2416.34 4394.69,2416.34 v1(4383.86,2427.17)
GPIO0_D0: CON1.29 R95591.2 U33.58 | length 5538.9
  Top w3.94: v1(4380.91,2446.85) 4380.91,2445.57 4415.75,2445.57 U33.58@4415.75,2444.29
  Top w7.87: CON1.29@1592.94,1876.36 1700.6,1768.7 1838.58,1768.7 1854.33,1752.95 R95591.2@1854.33,1691.93
  Power w3.94: 1613.79,1855.51 1645.29,1824.02 1734.15,1824.02 1872.05,1686.12 1872.05,1454.72 v1(1849.41,1432.09)
  Power w15.75: CON1.29@1592.94,1876.36 1613.79,1855.51
  Bottom w3.94: v1(1849.41,1432.09) 1857.28,1432.09 1870.08,1419.29 2042.32,1419.29 2340.55,1121.06 4565.94,1121.06 4710.63,1265.75 4710.63,2354.33 4621.06,2443.9 4383.86,2443.9 v1(4380.91,2446.85)
GPIO0_D3: CON1.40 J24.94 | length 3433
  Top w3.94: v1(3184.05,1646.34) 3184.05,1644.68 3190.77,1644.68 3501.38,1955.29 3501.38,2997.66 3357.28,3141.76 3357.28,3221.4 3379.98,3244.09 3443.9,3244.09 3462.01,3262.2 J24.94@3462.01,3288.58
  Bottom w3.94: 2066.18,1949.61 2039.37,1922.79 2039.37,1722.44 2187.01,1574.8 2395.67,1574.8 2459.65,1638.78 3176.49,1638.78 v1(3184.05,1646.34)
  Bottom w15.75: 2066.18,1949.61 CON1.40@2092.94,1976.36
GPIO1_A6_CAM1: R95595.1 U33.45 U90089.B3 | length 5699
  Top w3.94: R95595.1@535.43,1646.65 567.91,1614.17 567.91,1562.01 v1(554.13,1548.23) U90089.B3@538.39,1549.21 ; U33.45@4520.47,2349.8 4566.93,2349.8 v1(4566.93,2349.41)
  Bottom w3.94: v1(554.13,1548.23) 555.12,1547.24 555.12,1498.03 585.78,1467.37 702.29,1467.37 722.81,1446.85 749.63,1446.85 762.43,1459.65 1146.9,1459.65 1158.72,1471.46 2049.21,1471.46 2360.24,1160.43 4549.21,1160.43 4671.26,1282.48 4671.26,2298.23 4620.08,2349.41 v1(4566.93,2349.41)
GPIO1_A6_CAM1_E: R95570.1 R95595.2 U90089.B1 | length 2371.9
  Top w3.94: v1(125,2691.93) 125,2073.82 132.87,2065.94 132.87,1550.2 168.31,1514.76 449.8,1514.76 v1(484.25,1549.21) U90089.B1@499.02,1549.21 ; v1(437.99,2955.71) 437.99,2973.43 R95570.1@451.77,2987.2 ; v1(482.28,1645.67) 503.94,1645.67 R95595.2@503.94,1646.65
  Power w3.94: v1(482.28,1645.67) 482.28,1551.18 v1(484.25,1549.21)
  Bottom w3.94: v1(125,2691.93) 132.87,2691.93 167.32,2726.38 167.32,3020.98 198.51,3052.17 341.54,3052.17 v1(437.99,2955.71)
GPIO1_B1: CON1.22 U90133.A1 | length 1056.9
  Top w3.94: U90133.A1@662.4,1580.71 657.51,1585.6 657.51,1991.04 744.22,2077.76 1144.86,2077.76 1192.94,2029.67 1192.94,2009.84
  Top w15.75: CON1.22@1192.94,1976.36 1192.94,2009.84
GPIO1_B1_S: U33.40 U90133.A3 | length 5445.3
  Top w3.94: U90133.A3@701.77,1580.71 726.38,1580.71 737.2,1569.88 v1(737.2,1476.38) ; U33.40@4415.75,2302.56 4469.09,2302.56 v1(4477.36,2294.29)
  Bottom w3.94: v1(737.2,1476.38) 744.09,1483.27 1137.12,1483.27 1148.93,1495.08 2061.02,1495.08 2372.05,1184.06 4537.4,1184.06 4647.64,1294.29 4647.64,2266.73 4623.03,2291.34 4480.31,2291.34 v1(4477.36,2294.29)
GPIO1_B2_CAM1: R95594.1 U33.44 U90089.A3 | length 5727.8
  Top w3.94: R95594.1@535.43,1611.22 554.13,1592.52 v1(554.13,1568.9) U90089.A3@538.39,1568.9 ; U33.44@4415.75,2334.06 4436.16,2334.06 4444.63,2342.52 4467.52,2342.52 v1(4467.52,2340.55)
  Bottom w3.94: v1(554.13,1568.9) 569.88,1553.15 569.88,1540.35 562.99,1533.46 562.99,1501.97 589.72,1475.24 705.55,1475.24 726.07,1454.72 746.37,1454.72 759.17,1467.52 1143.64,1467.52 1155.45,1479.33 2053.15,1479.33 2364.17,1168.31 4545.28,1168.31 4663.39,1286.42 4663.39,2282.79 4625.31,2320.87 4517.72,2320.87 4492.13,2346.46 4475.53,2346.46 v1(4467.52,2340.55)
GPIO1_B2_CAM1_E: R95571.1 R95594.2 U90089.A1 | length 2249.3
  Top w3.94: v1(141.73,2681.1) 133.07,2672.44 133.07,2078.74 140.75,2071.06 140.75,1554.13 172.24,1522.64 437.99,1522.64 484.25,1568.9 U90089.A1@499.02,1568.9 499.02,1611.22 R95594.2@503.94,1611.22 ; R95571.1@415.35,2987.2 417.32,2985.24 v1(417.32,2955.71)
  Bottom w3.94: v1(141.73,2681.1) 177.17,2716.54 177.17,3019.68 201.77,3044.29 337.6,3044.29 417.32,2964.57 v1(417.32,2955.71)
GPIO1_B6_CAM2_CLK: J24.10 R715.1 | length 4284.2
  Top w3.94: v1(995.08,2947.83) 998.03,2950.79 R715.1@998.03,2963.58 ; J24.10@4123.43,3288.58 4123.43,3324.01 4147.84,3348.43 4209.45,3348.43 4225.39,3332.48 v1(4225.39,3296.26) ; v1(4198.82,2615.16) 4198.82,3080.71 4239.17,3121.06 4239.17,3163.39 v1(4217.52,3185.04)
  Power w3.94: v1(4217.52,3185.04) 4217.52,3288.39 v1(4225.39,3296.26)
  Bottom w3.94: v1(995.08,2947.83) 1025.59,2978.35 2653.85,2978.35 2857.59,2774.61 3315.94,2774.61 3462.6,2627.95 4184.06,2627.95 4196.85,2615.16 v1(4198.82,2615.16)
GPIO1_B7: J24.12 U90133.B3 | length 5126
  Top w3.94: U90133.B3@701.77,1561.02 v1(723.43,1561.02) ; v1(2034.45,2645.67) 2036.42,2645.67 2048.23,2633.86 2714.88,2633.86 2783.46,2702.45 2783.46,3008.49 2918.67,3143.7 v1(2963.58,3143.7) ; v1(4107.28,3322.83) 4107.68,3322.44 J24.12@4107.68,3288.58
  Power w3.94: v1(723.43,1561.02) 723.43,1744.09 v1(785.43,1806.1) ; v1(2963.58,3143.7) 3013.78,3093.5 3487.51,3093.5 3547.55,3033.46 4048.9,3033.46 4062.01,3046.57 4062.01,3207.99 4107.28,3253.26 v1(4107.28,3322.83)
  Bottom w3.94: v1(785.43,1806.1) 791.34,1800.2 1012.12,1800.2 1056.1,1844.18 1056.1,2561.7 1149.92,2655.51 2024.61,2655.51 v1(2034.45,2645.67)
GPIO1_B7_E: CON1.32 U90133.B1 | length 1606.6
  Top w3.94: U90133.B1@662.4,1561.02 649.63,1573.79 649.63,1994.3 740.96,2085.63 1493.11,2085.63 1516.73,2062.01 v1(1516.73,2054.13)
  Bottom w3.94: v1(1516.73,2054.13) 1516.73,2050.2 1678.35,2050.2 1692.94,2035.6 1692.94,2007.87
  Bottom w15.75: CON1.32@1692.94,1976.36 1692.94,2007.87
GPIO1_C1: J24.20 R159.1 U90133.C3 | length 8867.6
  Top w3.94: U90133.C3@701.77,1541.34 714.57,1528.54 714.57,1412.4 v1(707.68,1405.51) ; J24.20@4044.69,3288.58 4044.69,3246.96 4056.41,3235.24 4214.57,3235.24 4446.85,3002.95 4562.99,3002.95 v1(4581.69,3021.65) ; R159.1@5746.06,2490.16 5759.84,2503.94 v1(5759.84,2556.1)
  Bottom w3.94: v1(707.68,1405.51) 719.49,1393.7 751.97,1393.7 762.8,1404.53 1215.55,1404.53 1227.36,1416.34 1803.15,1416.34 1832.68,1386.81 2025.59,1386.81 2322.83,1089.57 3878.94,1089.57 3943.9,1024.61 4612.51,1024.61 4782.48,1194.57 4782.48,2627.28 4723.43,2686.33 4723.43,2798.03 4731.3,2805.9 4731.3,2826.57 4582.68,2975.2 4582.68,3016.73 v1(4581.69,3021.65) 4581.69,3064.96 4603.35,3086.61 4674.52,3086.61 4769.01,3181.1 4854.64,3181.1 4957.99,3284.45 5211.31,3284.45 5304.13,3191.62 5304.13,3000 5748.03,2556.1 v1(5759.84,2556.1)
GPIO1_C1_E: CON1.33 U90133.C1 | length 1796.8
  Top w3.94: U90133.C1@662.4,1541.34 641.76,1561.98 641.76,1997.56 737.7,2093.5 1496.65,2093.5 1524.21,2065.94 v1(1532.48,2065.94)
  Bottom w3.94: v1(1532.48,2065.94) 1540.16,2058.27 1698.43,2058.27 1744.09,2012.6 1744.09,1925.21 1767.73,1901.57
  Bottom w15.75: 1767.73,1901.57 CON1.33@1792.94,1876.36
GPIO1_C4: CON1.16 U90132.A1 | length 607.2
  Top w3.94: U90132.A1@783.46,1580.71 783.46,1784.33 755.08,1812.72 755.08,2008.5 774.93,2028.35 840.95,2028.35 870.48,1998.82
  Top w15.75: 870.48,1998.82 CON1.16@892.94,1976.36
GPIO1_C4_S: J24.79 U90132.A3 | length 4544.5
  Top w3.94: U90132.A3@822.83,1580.71 834.65,1592.52 834.65,1737.2 v1(855.31,1757.87) ; v1(3321.96,1578.95) 3321.96,1615.27 3399.61,1692.91 3399.61,1719.49 3612.2,1932.09 3612.2,3066.93 3572.24,3106.89 J24.79@3572.24,3184.65
  Bottom w3.94: v1(855.31,1757.87) 875.98,1737.2 1957.79,1737.2 2167.44,1527.56 2415.24,1527.56 2479.21,1591.54 3159.93,1591.54 3189.41,1562.05 3311.39,1562.05 3321.96,1572.63 v1(3321.96,1578.95)
GPIO1_C6: CON1.36 U90132.C1 | length 1738.7
  Top w3.94: U90132.C1@783.46,1541.34 763.35,1561.45 763.35,1782.18 739.24,1806.28 739.24,2014.93 773.52,2049.21 1144.69,2049.21 v1(1147.64,2052.17)
  Bottom w3.94: v1(1147.64,2052.17) 1147.64,2071.26 1170.87,2094.49 1774.81,2094.49 1869.69,1999.61
  Bottom w15.75: 1869.69,1999.61 CON1.36@1892.94,1976.36
GPIO1_C6_S: J24.75 U90132.C3 | length 4577.6
  Top w3.94: U90132.C3@822.83,1541.34 838.58,1541.34 850.39,1553.15 850.39,1706.69 v1(858.27,1714.57) ; v1(3344.98,1548.14) 3344.98,1614.55 3415.35,1684.93 3415.35,1711.61 3627.95,1924.21 3627.95,3074.8 3603.74,3099.02 J24.75@3603.74,3184.65
  Bottom w3.94: v1(858.27,1714.57) 859.18,1713.65 866.99,1721.46 1950.48,1721.46 2160.12,1511.81 2421.76,1511.81 2485.74,1575.79 3153.4,1575.79 3183.05,1546.15 3342.99,1546.15 v1(3344.98,1548.14)
GPIO1_D2: CON1.38 U90132.D1 | length 1867
  Top w3.94: U90132.D1@783.46,1521.65 755.47,1549.64 755.47,1778.92 731.03,1803.36 731.03,2017.85 770.26,2057.09 1122.05,2057.09 v1(1128.94,2063.98)
  Bottom w3.94: v1(1128.94,2063.98) 1167.32,2102.36 1866.94,2102.36 1967.73,2001.57
  Bottom w15.75: 1967.73,2001.57 CON1.38@1992.94,1976.36
GPIO1_D2_S: J24.83 U90132.D3 | length 4577.2
  Top w3.94: U90132.D3@822.83,1521.65 830.7,1521.65 858.27,1549.21 858.27,1694.88 876.97,1713.58 v1(876.97,1757.87) ; v1(3302.38,1575.89) 3308.47,1581.98 3308.47,1613.59 3391.73,1696.85 3391.73,1723.43 3604.33,1936.02 3604.33,3058.35 3540.75,3121.93 J24.83@3540.75,3184.65
  Bottom w3.94: v1(876.97,1757.87) 889.76,1745.08 1961.05,1745.08 2170.7,1535.43 2411.98,1535.43 2475.95,1599.41 3163.19,1599.41 3186.71,1575.89 v1(3302.38,1575.89)
GPIO1_D5: CON1.18 U90132.B1 | length 746.4
  Top w3.94: U90132.B1@783.46,1561.02 771.22,1573.26 771.22,1785.44 747.17,1809.49 747.17,2011.73 771.67,2036.22 933.08,2036.22 970.48,1998.82
  Top w15.75: 970.48,1998.82 CON1.18@992.94,1976.36
GPIO1_D5_S: J24.77 U90132.B3 | length 4550.6
  Top w3.94: U90132.B3@822.83,1561.02 842.52,1580.7 842.52,1724.41 v1(852.36,1734.25) ; v1(3329.67,1560.76) 3336.95,1568.04 3336.95,1617.66 3407.48,1688.19 3407.48,1715.55 3620.08,1928.15 3620.08,3070.87 3587.99,3102.95 J24.77@3587.99,3184.65
  Bottom w3.94: v1(852.36,1734.25) 857.28,1729.33 1953.74,1729.33 2163.39,1519.68 2418.5,1519.68 2482.48,1583.66 3156.67,1583.66 3186.2,1554.13 3323.03,1554.13 v1(3329.67,1560.76)
GPIO3_B7: CON1.26 J24.6 R95592.2 | length 4625.6
  Top w3.94: 1368.35,1951.77 1353.35,1936.77 1353.35,1858.27 1412.4,1799.21 1646.65,1799.21 1752.95,1692.91 v1(1821.85,1692.91) ; v1(1994.09,1639.76) 1994.09,1662.4 R95592.2@1964.57,1691.93 1964.57,1767.72 2001.97,1805.12 2528.54,1805.12 2730.31,2006.89 v1(2738.19,2006.89) ; v1(2771.65,2635.83) 2809.06,2673.23 2809.06,3011.81 2909.45,3112.2 2960.63,3112.2 v1(2961.61,3113.19) ; v1(4142.72,3323.82) 4154.53,3312.01 4154.53,3288.58 J24.6@4154.92,3288.58
  Top w19.68: 1368.35,1951.77 CON1.26@1392.94,1976.36
  Power w3.94: v1(2961.61,3113.19) 2960.63,3112.2 2987.2,3085.63 3484.25,3085.63 3544.29,3025.59 4052.17,3025.59 4069.88,3043.31 4069.88,3204.72 4130.91,3265.75 4130.91,3304.13 4142.72,3315.94 v1(4142.72,3323.82)
  Bottom w3.94: v1(1821.85,1692.91) 1940.94,1692.91 v1(1994.09,1639.76) ; v1(2738.19,2006.89) 2738.19,2032.48 2722.44,2048.23 2722.44,2301.18 2738.19,2316.93 2738.19,2594.49 2771.65,2627.95 v1(2771.65,2635.83)
GPIO3_C0: CON1.35 J24.4 R95593.2 | length 4030.1
  Top w3.94: 1917.76,1901.18 1937.84,1921.26 2020.67,1921.26 2041.34,1900.59 2041.34,1850 2069.49,1821.85 2490.16,1821.85 2689.96,2021.65 2752.95,2021.65 v1(2752.95,2020.67) ; v1(2770.67,2657.48) 2781.5,2657.48 2798.23,2674.21 2798.23,3012.12 2912.09,3125.98 v1(2945.87,3125.98) ; v1(4170.28,3320.87) 4170.67,3320.87 J24.4@4170.67,3288.58
  Top w9.06: CON1.35@1892.94,1876.36 1928.15,1841.15 R95593.2@1928.15,1691.93
  Top w15.75: CON1.35@1892.94,1876.36 1917.76,1901.18
  Power w3.94: v1(2945.87,3125.98) 2945.87,3106.5 2974.61,3077.76 3480.99,3077.76 3541.03,3017.72 4055.43,3017.72 4077.76,3040.05 4077.76,3201.46 4138.78,3262.49 4138.78,3300.2 4159.45,3320.87 v1(4170.28,3320.87)
  Bottom w3.94: v1(2752.95,2020.67) 2752.95,2029.53 2730.31,2052.17 2730.31,2297.24 2746.06,2312.99 2746.06,2590.55 2785.43,2629.92 2785.43,2642.72 v1(2770.67,2657.48)
GPIO4_A4: CON1.15 J24.38 | length 4532.8
  Top w3.94: v1(2044.29,2677.17) 2044.29,2668.25 2062.93,2649.61 2708.35,2649.61 2766.73,2707.99 2766.73,3040.3 2926.24,3199.8 v1(2949.8,3199.8) ; v1(3902.56,3244.09) 3902.95,3244.49 J24.38@3902.95,3288.58
  Power w3.94: v1(2949.8,3199.8) 2959.08,3199.8 3033.88,3125 3500.56,3125 3560.6,3064.96 3880.91,3064.96 3906.5,3090.55 3906.5,3240.16 v1(3902.56,3244.09)
  Bottom w3.94: 892.94,1843.7 892.94,1838.36 902.56,1828.74 1018.39,1828.74 1040.35,1850.7 1040.35,2568.22 1145.36,2673.23 2040.35,2673.23 v1(2044.29,2677.17)
  Bottom w15.75: 892.94,1843.7 CON1.15@892.94,1876.36
GPIO4_A5: CON1.13 J24.40 | length 4600.3
  Top w3.94: v1(2063.98,2668.31) 2074.8,2657.48 2705.09,2657.48 2758.86,2711.25 2758.86,3043.56 2925.2,3209.9 2935.29,3209.9 v1(2944.88,3219.49) ; v1(3886.81,3255.91) 3886.81,3288.58 J24.40@3887.2,3288.58
  Power w3.94: v1(2944.88,3219.49) 2950.53,3219.49 3037.15,3132.87 3503.82,3132.87 3563.86,3072.83 3876.97,3072.83 3898.62,3094.49 3898.62,3221.46 3886.81,3233.27 v1(3886.81,3255.91)
  Bottom w3.94: 816.94,1852.36 848.44,1820.87 1021.65,1820.87 1048.23,1847.44 1048.23,2564.96 1146.65,2663.39 2054.98,2663.39 v1(2063.98,2668.31)
  Bottom w15.75: CON1.13@792.94,1876.36 816.94,1852.36
GPIO4_A6: CON1.11 J24.89 | length 4482
  Top w3.94: v1(3273.62,1627.61) 3273.62,1628.94 3288.39,1628.94 3368.11,1708.66 3368.11,1735.24 3580.71,1947.83 3580.71,3048.57 3493.5,3135.77 J24.89@3493.5,3184.65
  Bottom w3.94: 716.15,1853.15 733.46,1835.84 733.46,1814.45 763.47,1784.45 1955.09,1784.45 2180.48,1559.06 2402.19,1559.06 2466.17,1623.03 3269.05,1623.03 v1(3273.62,1627.61)
  Bottom w15.75: CON1.11@692.94,1876.36 716.15,1853.15
GPIO4_A7: CON1.7 J24.87 | length 4694
  Top w3.94: v1(3280.66,1608.98) 3280.66,1614.17 3285.43,1614.17 3375.98,1704.72 3375.98,1731.3 3588.58,1943.9 3588.58,3051.83 3509.25,3131.16 J24.87@3509.25,3184.65
  Bottom w3.94: 516.94,1852.36 592.73,1776.57 1951.83,1776.57 2177.22,1551.18 2405.45,1551.18 2469.43,1615.16 3169.71,1615.16 3180.32,1604.55 3276.23,1604.55 v1(3280.66,1608.98)
  Bottom w15.75: CON1.7@492.94,1876.36 516.94,1852.36
GSENSOR_INT: R95541.2 U33.29 | length 2329.5
  Top w3.94: v1(2650.59,2927.17) 2670.28,2946.85 2670.28,2963.58 R95541.2@2674.21,2967.52 ; v1(4478.35,2194.88) 4478.35,2201.77 4500.39,2223.82 U33.29@4520.47,2223.82
  Bottom w3.94: v1(2650.59,2927.17) 2659.45,2927.17 2867.13,2719.49 3257.57,2719.49 3635.52,2341.54 4267.04,2341.54 4303.46,2305.12 4439.96,2305.12 4467.52,2277.56 4467.52,2269.68 4437.99,2240.16 4437.99,2197.83 4442.91,2192.91 4476.38,2192.91 v1(4478.35,2194.88)
HDMI0_SBDN: C90430.2 ED1.1 J1.19 R95282.2 | length 316.7
  Top w3.94: C90430.2@367.13,333.66 394.69,333.66 R95282.2@397.15,336.12 438.48,336.12 ED1.1@439.96,334.65
  Top w9.84: ED1.1@439.96,334.65 439.96,313.98 452.76,301.18 541.34,301.18 590.56,251.97 J1.19@590.56,206.69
